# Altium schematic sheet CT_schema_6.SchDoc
size 293 x 258 mm
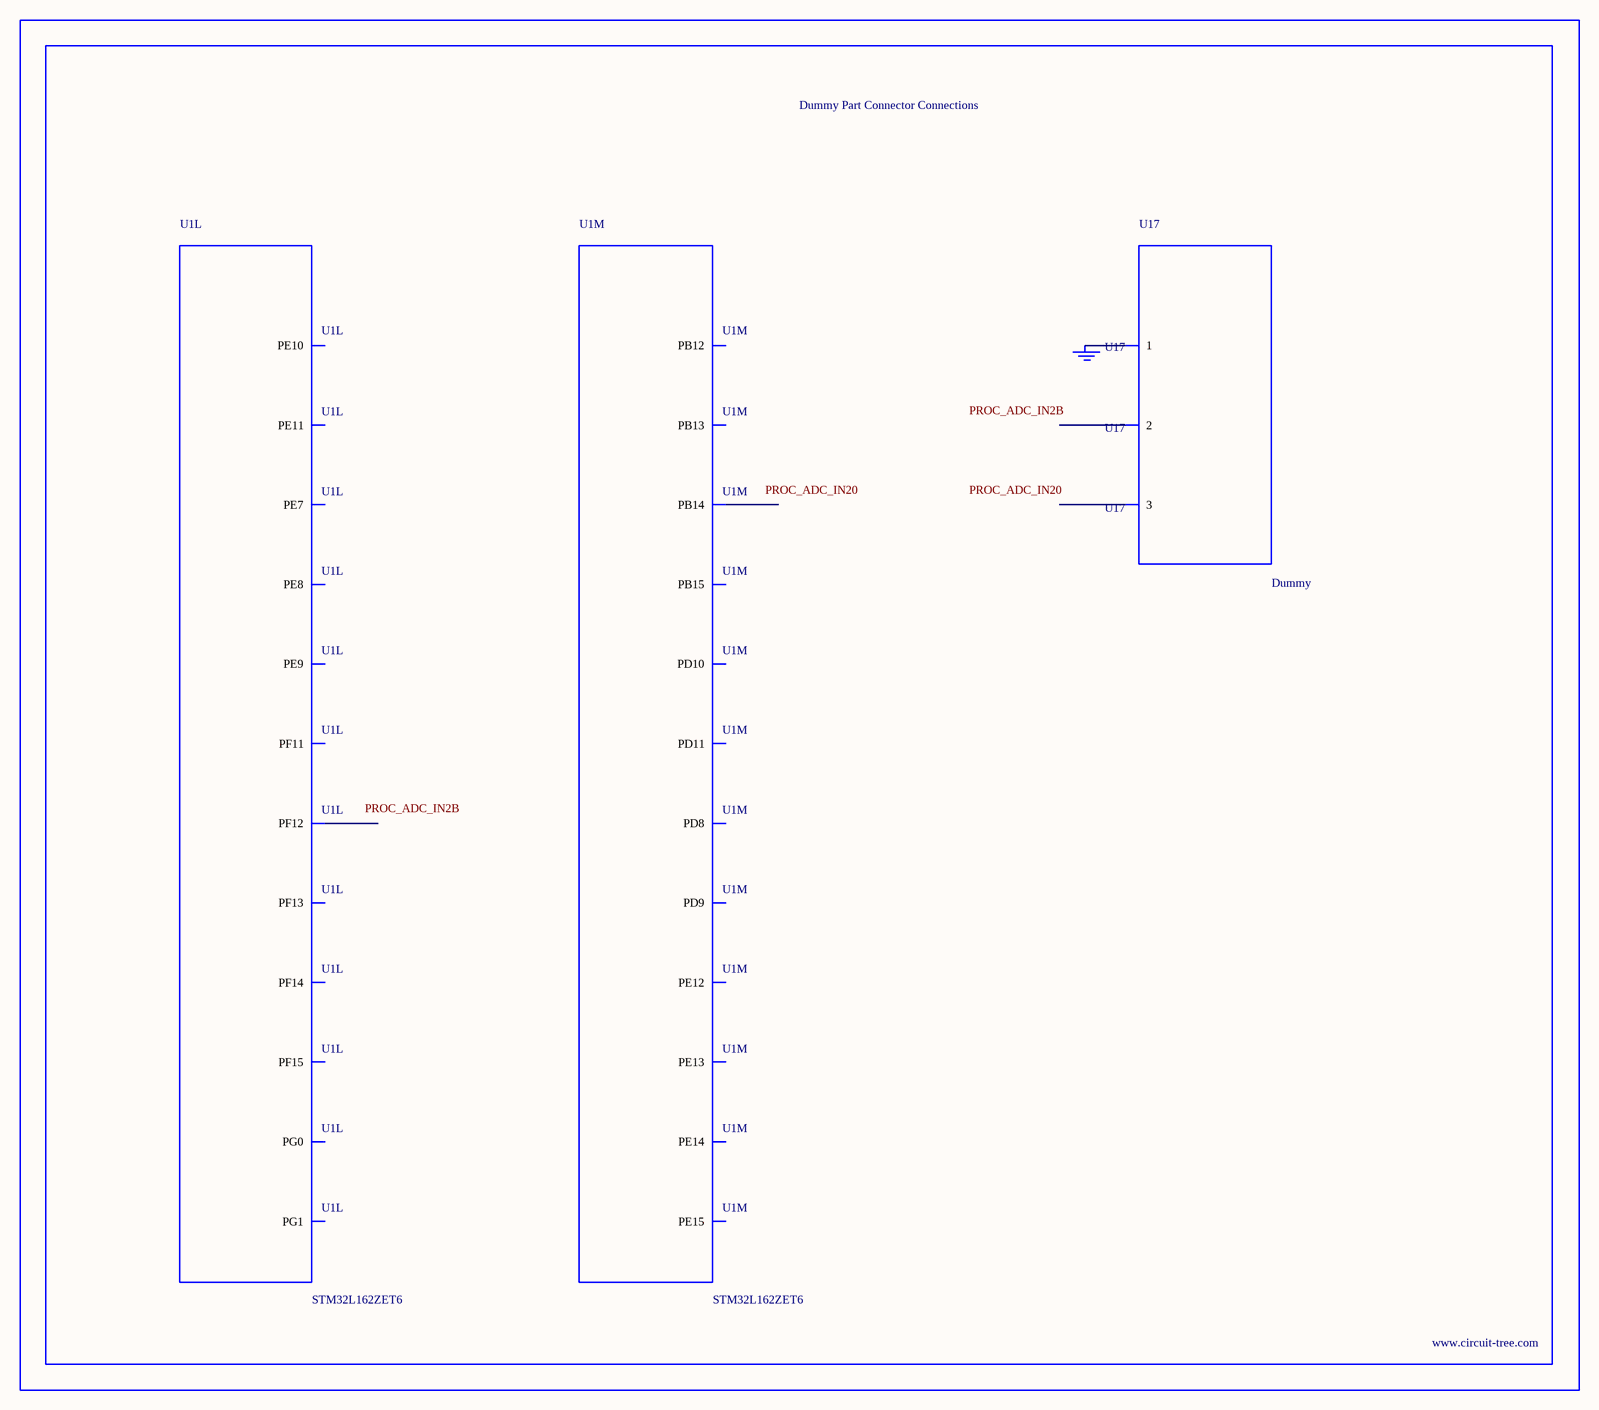
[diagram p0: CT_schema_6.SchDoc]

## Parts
BORDER5  (no value)
GND_INSTANCE_5_0  (no value)
U1  STM32L162ZET6  [LQFP144]  (parts L,M of 13)
U17  Dummy  [DUMMY_PACKAGE_165]

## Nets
NetGND_INSTANCE_5_0_0: GND_INSTANCE_5_0.0(GND) U17.1

Not connected (* = marked no-connect by the designer): U1 49(PF11) 50(PF12) 53(PF13) 54(PF14) 55(PF15) 56(PG0) 57(PG1) 58(PE7) 59(PE8) 60(PE9) 63(PE10) 64(PE11) 65(PE12) 66(PE13) 67(PE14) 68(PE15) 73(PB12) 74(PB13) 75(PB14) 76(PB15) 77(PD8) 78(PD9) 79(PD10) 80(PD11); U17 2 3

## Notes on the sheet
- Labels drawn without touching a wire or pin: PROC_ADC_IN2B, PROC_ADC_IN20

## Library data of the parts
BORDER5 = BORDER_PAGE5
GND_INSTANCE_5_0 = GND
